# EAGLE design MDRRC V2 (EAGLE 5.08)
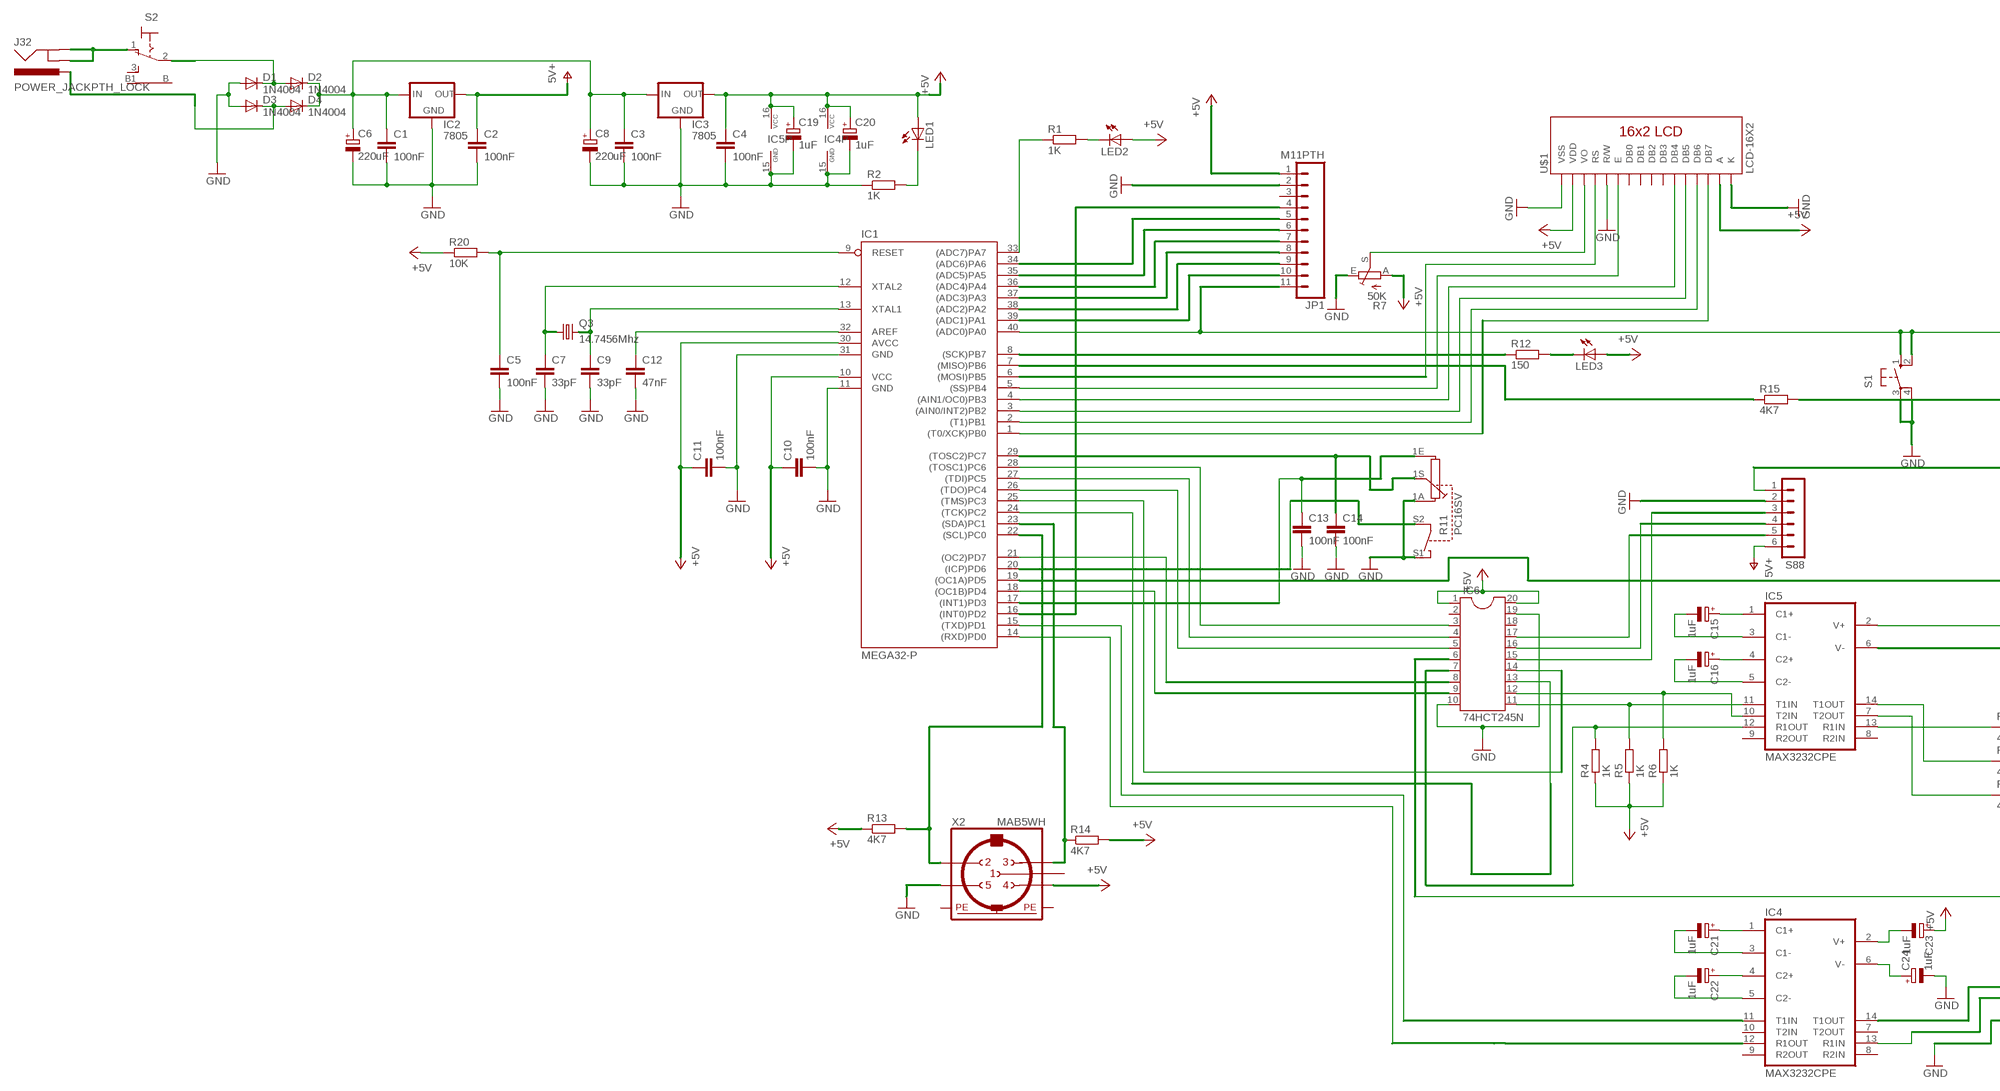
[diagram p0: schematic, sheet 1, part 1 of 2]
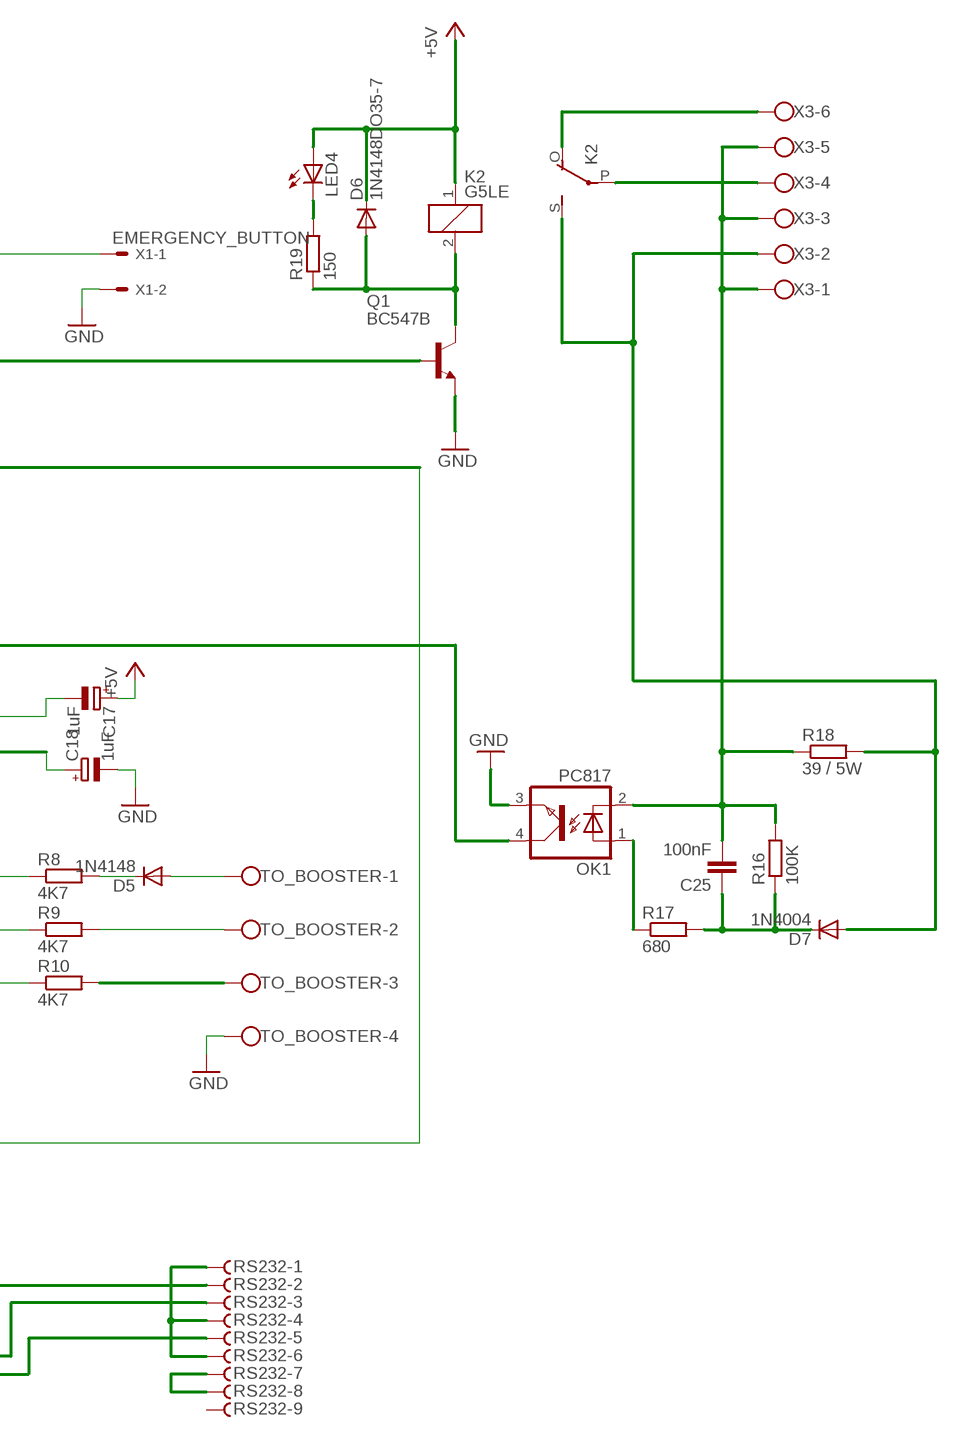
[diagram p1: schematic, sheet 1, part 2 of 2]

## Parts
C1  100nF  C-EU025-025X050  [C025-025X050]
C2  100nF  C-EU025-025X050  [C025-025X050]
C3  100nF  C-EU025-025X050  [C025-025X050]
C4  100nF  C-EU025-025X050  [C025-025X050]
C5  100nF  C-EU025-025X050  [C025-025X050]
C6  220uF  CPOL-EUE2.5-5  [E2,5-5]
C7  33pF  C-EU025-025X050  [C025-025X050]
C8  220uF  CPOL-EUE2.5-5  [E2,5-5]
C9  33pF  C-EU025-025X050  [C025-025X050]
C10  100nF  C-EU025-025X050  [C025-025X050]
C11  100nF  C-EU025-025X050  [C025-025X050]
C12  47nF  C-EU025-025X050  [C025-025X050]
C13  100nF  C-EU025-025X050  [C025-025X050]
C14  100nF  C-EU025-025X050  [C025-025X050]
C15  1uF  CPOL-EUE1.8-4  [E1,8-4]
C16  1uF  CPOL-EUE1.8-4  [E1,8-4]
C17  1uF  CPOL-EUE1.8-4  [E1,8-4]
C18  1uF  CPOL-EUE1.8-4  [E1,8-4]
C19  1uF  CPOL-EUE1.8-4  [E1,8-4]
C20  1uF  CPOL-EUE1.8-4  [E1,8-4]
C21  1uF  CPOL-EUE1.8-4  [E1,8-4]
C22  1uF  CPOL-EUE1.8-4  [E1,8-4]
C23  1uF  CPOL-EUE1.8-4  [E1,8-4]
C24  1uF  CPOL-EUE1.8-4  [E1,8-4]
C25  100nF  C-EU025-025X050  [C025-025X050]
D1  1N4004  [DO41-10]
D2  1N4004  [DO41-10]
D3  1N4004  [DO41-10]
D4  1N4004  [DO41-10]
D5  1N4148  1N4148DO35-10  [DO35-10]
D6  1N4148DO35-7  [DO35-7]
D7  1N4004  [DO41-10]
IC1  MEGA32-P  [DIL40]
IC2  7805  78XXS  [78XXS]
IC3  7805  78XXS  [78XXS]
IC4  MAX3232CPE  [DIL16]
IC5  MAX3232CPE  [DIL16]
IC6  74HCT245N  DIL20  [DIL20]
J32  POWER_JACKPTH_LOCK  [POWER_JACK_PTH_LOCK]
JP1  M11PTH  [1X11]
K2  G5LE  [G5LE]
LED1  LED3MM  [LED3MM]
LED2  LED3MM  [LED3MM]
LED3  LED3MM  [LED3MM]
LED4  LED3MM  [LED3MM]
OK1  PC817  [DIL04]
Q1  BC547B  [TO92]
Q3  14.7456Mhz  CRYSTALHC18U-V  [HC18U-V]
R1  1K  R-EU_0207/10  [0207/10]
R2  1K  R-EU_0207/10  [0207/10]
R4  1K  R-EU_0207/10  [0207/10]
R5  1K  R-EU_0207/10  [0207/10]
R6  1K  R-EU_0207/10  [0207/10]
R7  50K  TRIM_EU-CA6V  [CA6V]
R8  4K7  R-EU_0207/10  [0207/10]
R9  4K7  R-EU_0207/10  [0207/10]
R10  4K7  R-EU_0207/10  [0207/10]
R11  PC16SV  [PC16SV]
R12  150  R-EU_0207/10  [0207/10]
R13  4K7  R-EU_0207/10  [0207/10]
R14  4K7  R-EU_0207/10  [0207/10]
R15  4K7  R-EU_0207/10  [0207/10]
R16  100K  R-EU_0207/10  [0207/10]
R17  680  R-EU_0207/10  [0207/10]
R18  39 / 5W  R-EU_V235/17  [V235/17]
R19  150  R-EU_0207/10  [0207/10]
R20  10K  R-EU_0207/2V  [0207/2V]
RS232  F09HPS  [F09HP]
S1  10-XX  [B3F-10XX]
S2  LPV-1  [LPV-1]
S88  MA06-1  [MA06-1]
TO_BOOSTER  W237-04P  [W237-4P]
U$1  LCD-16X2  [LCD-16X2]
X1  EMERGENCY_BUTTON  22-23-2021  [22-23-2021]
X2  MAB5WH  [MAB5WH]
X3  W237-06P  [W237-6P]

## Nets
+5V: C4.1 C10.1 C11.1 C17.+ C19.+ C20.+ C23.+ D6.C IC1.10(VCC) IC1.30(AVCC) IC3.OUT IC4.16(VCC) IC5.16(VCC) IC6.1 IC6.20 JP1.1 K2.1 LED1.A LED2.A LED3.A LED4.A R4.1 R5.1 R6.1 R7.A R13.1 R14.2 R20.1 U$1.2(VDD) U$1.15(A) X2.4
GND: C1.2 C2.2 C3.2 C4.2 C5.2 C6.- C7.2 C8.- C9.2 C10.2 C11.2 C12.2 C13.2 C14.2 C18.- C19.- C20.- C24.- D1.A D3.A IC1.11(GND) IC1.31(GND) IC2.GND IC3.GND IC4.15(GND) IC5.15(GND) IC6.10 IC6.19 JP1.2 OK1.3(EMIT) Q1.1(E) R2.1 R7.E R11.1A R11.S1 RS232.5 S1.3(P) S1.4(P1) S88.2 TO_BOOSTER.4 U$1.1(VSS) U$1.5(R/W) U$1.16(K) X1.2 X2.5
N$1: D1.C D2.A S2.2(P)
N$2: D3.C D4.A J32.PWR
N$3: C7.1 IC1.12(XTAL2) Q3.1
N$4: C1.1 C3.1 C6.+ C8.+ D2.C D4.C IC2.IN IC3.IN
N$5: C9.1 IC1.13(XTAL1) Q3.2
N$6: C12.1 IC1.32(AREF)
N$7: LED1.K(C) R2.2
N$8: C5.1 IC1.9(RESET) R20.2
N$9: IC1.33((ADC7)PA7) R1.1
N$10: LED2.K(C) R1.2
N$11: IC1.40((ADC0)PA0) JP1.11 S1.1(S) S1.2(S1) X1.1
N$12: IC1.8((SCK)PB7) R12.1
N$13: LED3.K(C) R12.2
N$14: IC5.12(R1OUT) IC6.7 R4.2
N$15: IC1.28((TOSC1)PC6) IC6.3
N$16: IC1.27((TDI)PC5) IC6.4
N$17: IC1.26((TDO)PC4) IC6.5
N$18: IC1.21((OC2)PD7) IC6.8
N$19: IC1.18((OC1B)PD4) IC6.9
N$20: IC1.25((TMS)PC3) IC6.14
N$23: IC5.11(T1IN) IC6.11 R5.2
N$24: IC5.10(T2IN) IC6.12 R6.2
N$27: C16.- IC5.5(C2-)
N$28: C15.- IC5.3(C1-)
N$29: C15.+ IC5.1(C1+)
N$30: C16.+ IC5.4(C2+)
N$31: C17.- IC5.2(V+)
N$34: IC6.15 S88.3
N$37: C21.+ IC4.1(C1+)
N$38: C21.- IC4.3(C1-)
N$39: C22.+ IC4.4(C2+)
N$40: C22.- IC4.5(C2-)
N$41: C23.- IC4.2(V+)
N$42: C24.+ IC4.6(V-)
N$43: IC1.15((TXD)PD1) IC4.11(T1IN)
N$45: IC4.14(T1OUT) RS232.2
N$46: IC4.13(R1IN) RS232.3
N$47: IC1.1((T0/XCK)PB0) U$1.14(DB7)
N$48: IC1.2((T1)PB1) U$1.13(DB6)
N$49: IC1.3((AIN0/INT2)PB2) U$1.12(DB5)
N$50: IC1.4((AIN1/OC0)PB3) U$1.11(DB4)
N$51: IC1.5((SS)PB4) U$1.6(E)
N$52: IC1.6((MOSI)PB5) U$1.4(RS)
N$53: R7.S U$1.3(VO)
N$54: IC5.14(T1OUT) R9.1
N$55: IC5.7(T2OUT) R10.1
N$56: IC5.13(R1IN) R8.1
N$57: R10.2 TO_BOOSTER.3
N$58: R9.2 TO_BOOSTER.2
N$59: D5.C R8.2
N$60: D5.A TO_BOOSTER.1
N$62: IC6.16 S88.4
N$63: IC6.17 S88.5
N$64: IC6.6 S88.1
N$67: IC1.7((MISO)PB6) R15.1
N$68: RS232.1 RS232.4 RS232.6
N$69: RS232.7 RS232.8
N$72: IC1.39((ADC1)PA1) JP1.10
N$73: IC1.38((ADC2)PA2) JP1.9
N$74: IC1.14((RXD)PD0) IC4.12(R1OUT)
N$75: IC1.37((ADC3)PA3) JP1.8
N$77: IC1.24((TCK)PC2) IC6.13
N$82: IC1.22((SCL)PC0) R13.2 X2.2
N$83: J32.GND J32.GNDBREAK S2.1(O)
N$84: IC1.20((ICP)PD6) R11.S2
N$85: C13.1 IC1.17((INT1)PD3) R11.1E
N$86: C14.1 IC1.29((TOSC2)PC7) R11.1S
N$87: IC1.36((ADC4)PA4) JP1.7
N$88: IC1.19((OC1A)PD5) OK1.4(COL)
N$91: IC1.35((ADC5)PA5) JP1.6
N$92: IC1.34((ADC6)PA6) JP1.5
N$96: IC1.16((INT0)PD2) JP1.4
N$98: IC1.23((SDA)PC1) R14.1 X2.3
N$100: C18.+ IC5.6(V-)
N$101: Q1.2(B) R15.2
N$102: D6.A K2.2 Q1.3(C) R19.1
N$105: K2.P(2:P) X3.4
N$108: K2.O(2:O) X3.6
N$113: C25.2 OK1.2(C) R16.2 R18.1 X3.1 X3.3 X3.5
N$114: OK1.1(A) R17.1
N$115: C25.1 D7.C R16.1 R17.2
N$116: D7.A K2.S(2:S) R18.2 X3.2
N$117: LED4.K(C) R19.2
V+: C2.1 IC2.OUT S88.6 ; supply symbol labelled 5V+
Unconnected: IC4.7(T2OUT) IC4.8(R2IN) IC4.9(R2OUT) IC4.10(T2IN) IC5.8(R2IN) IC5.9(R2OUT) IC6.2 IC6.18 JP1.3 RS232.9 S2.3(S) S2.B S2.B1 U$1.7(DB0) U$1.8(DB1) U$1.9(DB2) U$1.10(DB3) X2.1

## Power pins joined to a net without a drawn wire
PE: X2.PE X2.PE@(PE)

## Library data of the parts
C1-C5 C7 C9-C14 C25 = rcl:C-EU: CAPACITOR, European symbol
C6 C8 C15-C24 = rcl:CPOL-EU: POLARIZED CAPACITOR, European symbol
D1-D4 D7 = diode:1N4004: DIODE
D5 D6 = diode:1N4148: DIODE
IC1 = atmel:MEGA32-P: MICROCONTROLLER 32 Kbytes FLASH 2 Kbytes SRAM 1 Kbytes EEPROM USART 8-channel 10 bit ADC Source: www.atmel.com .. doc2503.pdf
IC2 IC3 = v-reg:78XXS: VOLTAGE REGULATOR
IC4 IC5 = maxim:MAX3232*: True RS-232 Transceivers 3.0V to 5.5V, Low-Power up to 1Mbps, Using Four 0.1µF External Capacitors Source: http://pdfserv.maxim-ic.com/en/ds/MAX3222-MAX3241.pdf
IC6 = ic-package:DIL20: Dual In Line / Socket
J32 = SparkFun:POWER_JACK: Power Jack This is the standard 5.5mm barrel jack for power. The PTH is the most common, proven, reliable, footprint. All others are experimental. The Slot footprint only works if the mill layer is transmitted to the PCB fab house so be warned. Spark Fun Electronics SKU : PRT-00119. Mating wall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
JP1 = SparkFun:M11: Header 11 Standard 11-pin 0.1" header. Use with straight break away headers (SKU : PRT-00116), right angle break away headers (PRT-00553), swiss pins (PRT-00743), machine pins (PRT-00117), and female headers (PRT-00115).
K2 = relay:G5LE: RELAY 1 x switch, 10 A/120 V AC, 8 A/30 V DC, Omron
LED1-LED4 = led:LED: LED
OK1 = optocoupler:PC817: SHARP OPTO COUPLER
Q1 = transistor-npn:BC547*: NPN Transistor
Q3 = crystal:CRYSTAL: CRYSTAL
R1 R2 R4-R6 R8-R10 R12-R14 R16 R17 R19 R20 = rcl:R-EU_: RESISTOR, European symbol
R7 = pot:TRIM_EU-: POTENTIOMETER
R11 = rotary_voti:PC16SV: POTENTIOMETER vertical single carbon potentiometer with switch, 16 mm
R15 R18 = resistor:R-EU_: RESISTOR, European symbol
RS232 = con-subd:F09?S: SUB-D
S1 = switch-omron:10-XX: OMRON SWITCH
S2 = switch:LPV-1: TOGGLE SWITCH
S88 = con-lstb:MA06-1: PIN HEADER
TO_BOOSTER = con-wago-508:W237-04P: WAGO SREW CLAMP
U$1 = SparkFun:LCD-16X2
X1 = con-molex:22-23-2021: .100" (2.54mm) Center Header - 2 Pin
X2 = con_midi:MAB5WH: Female CONNECTOR 5 pins with shield, horizontal (DIN 45327)
X3 = con-wago-508:W237-06P: WAGO SREW CLAMP

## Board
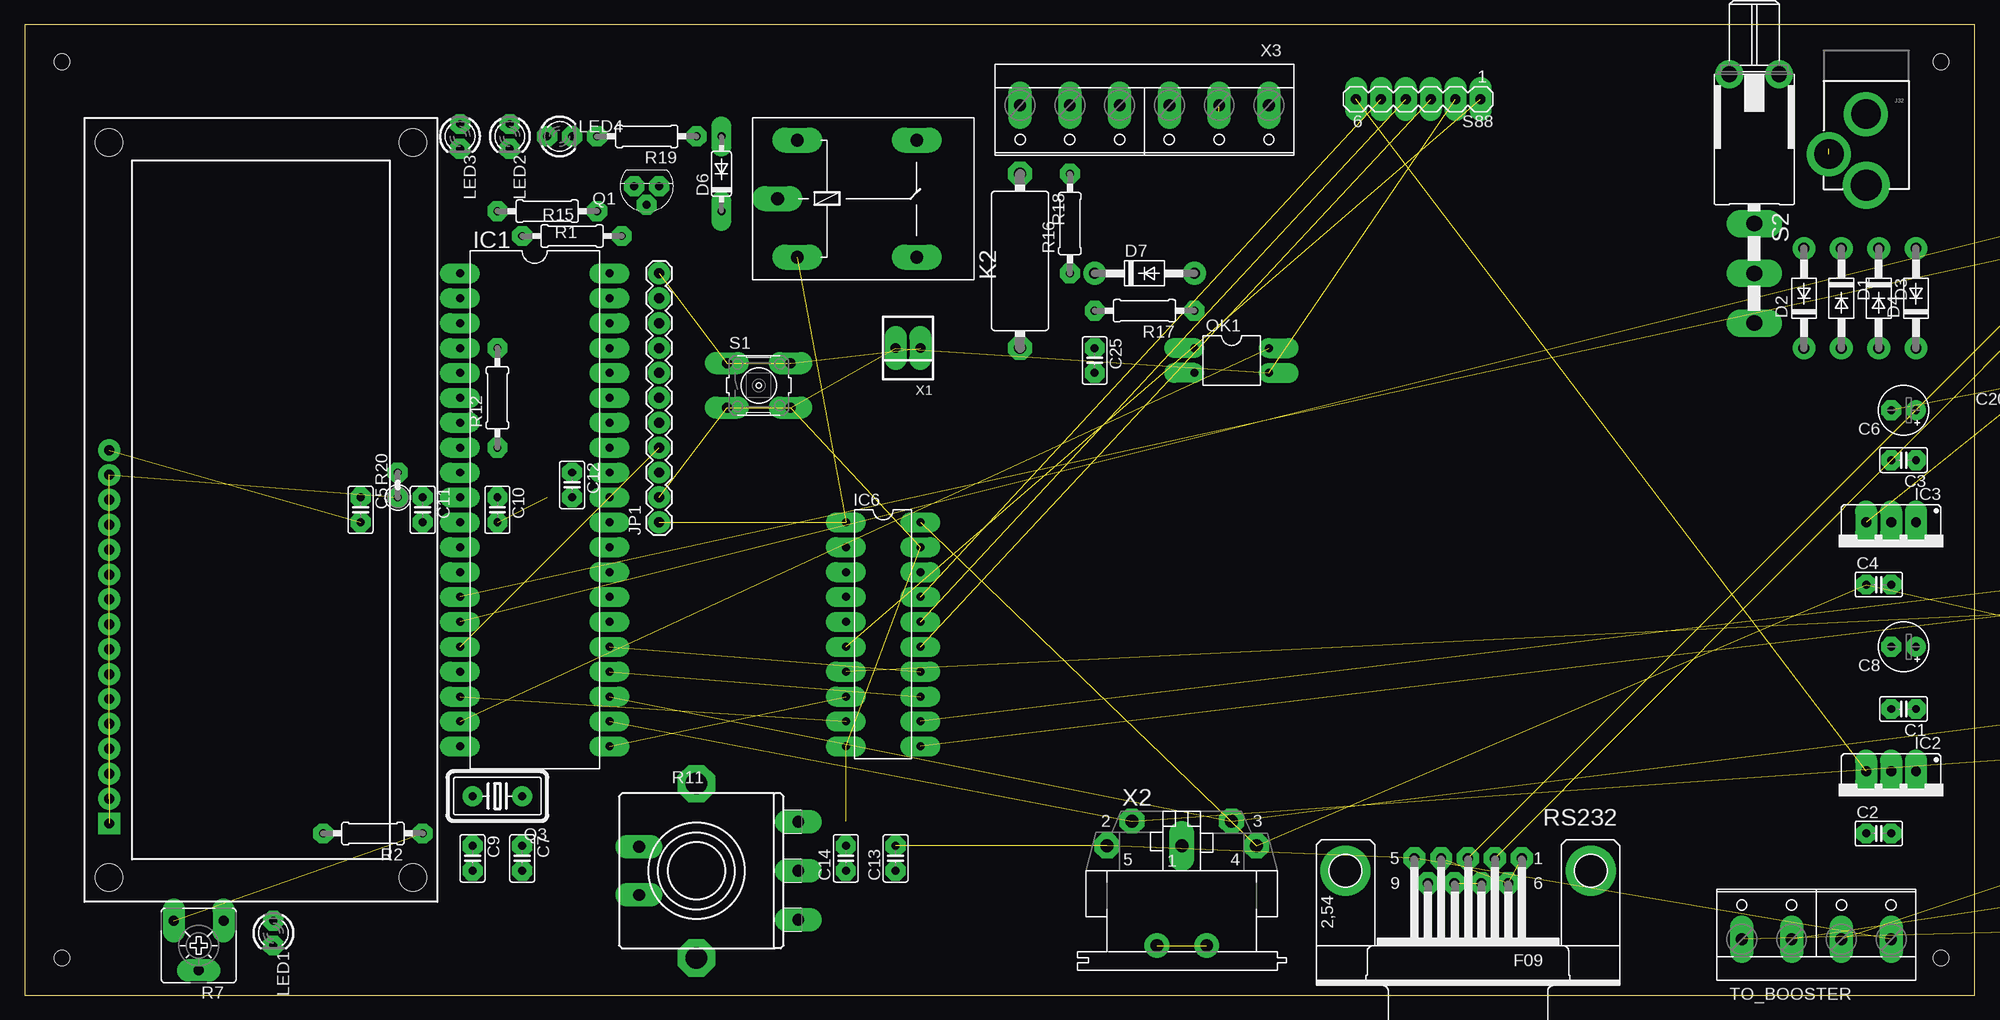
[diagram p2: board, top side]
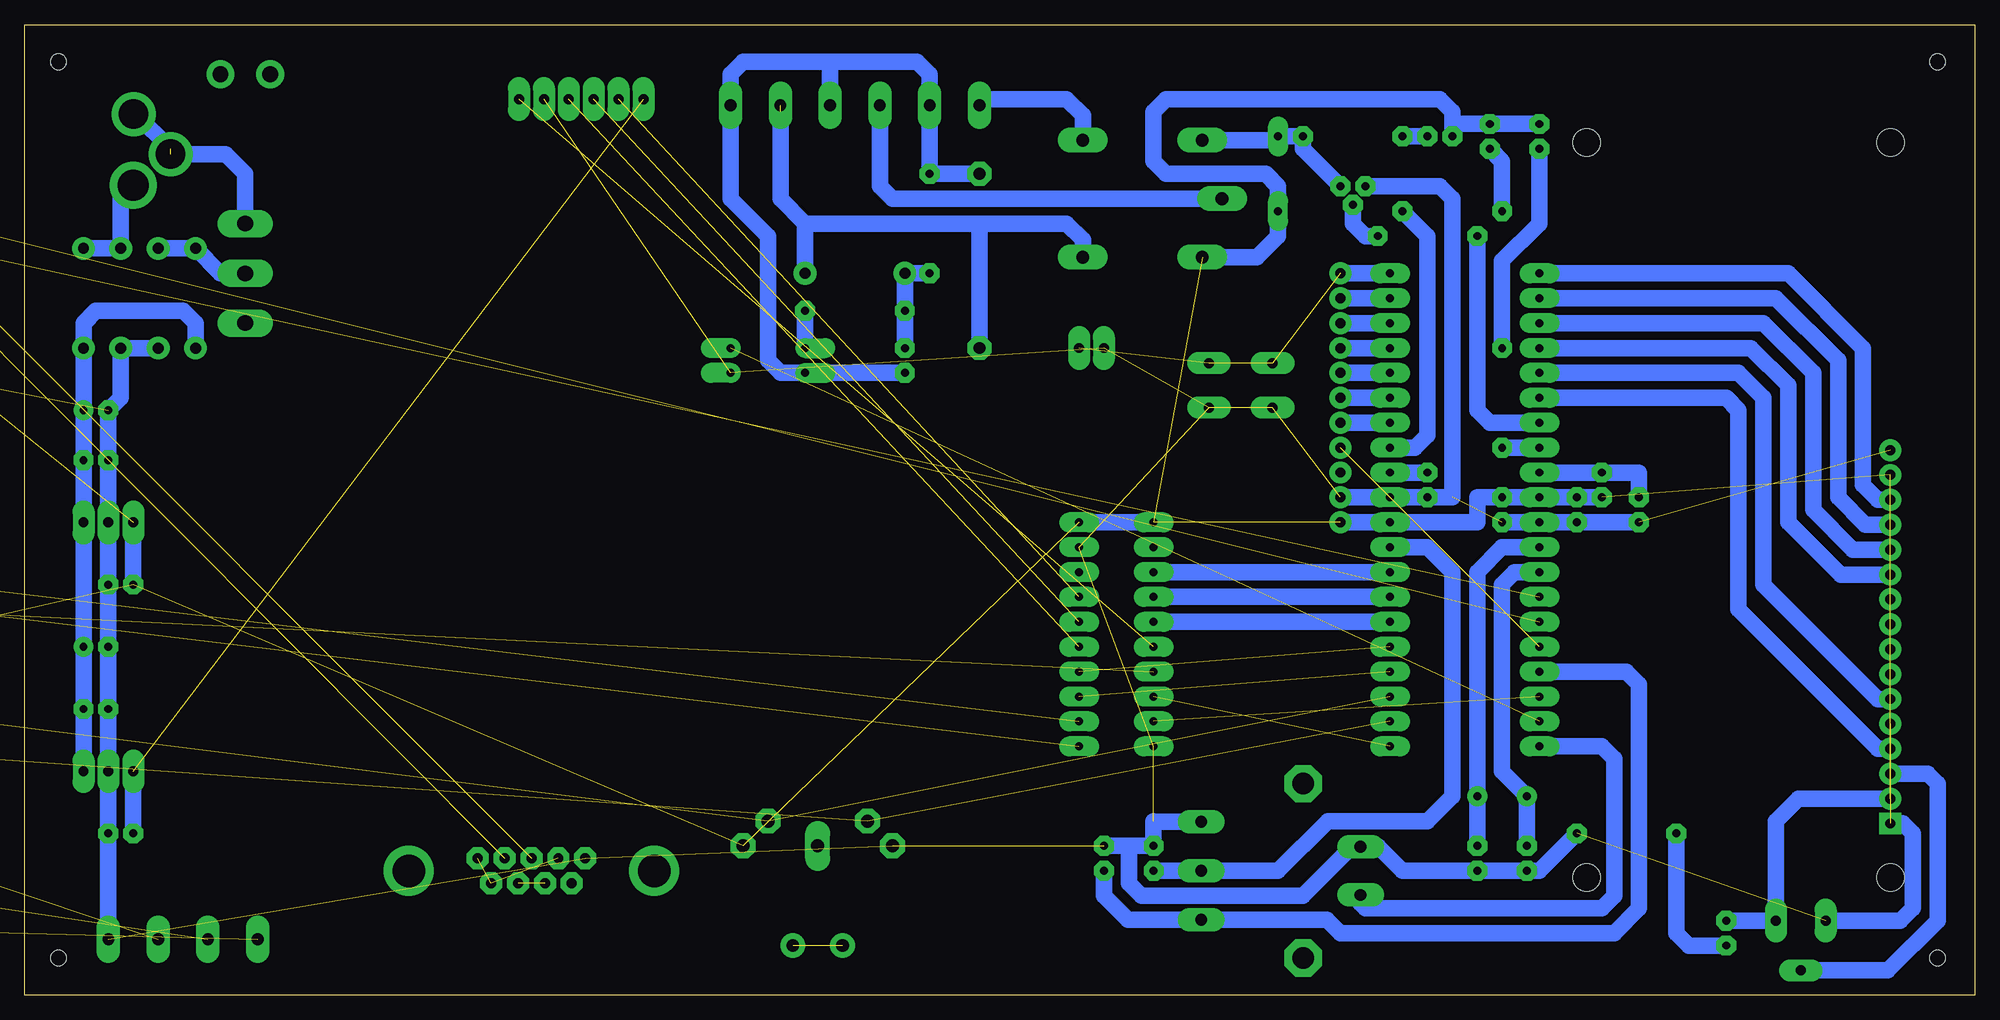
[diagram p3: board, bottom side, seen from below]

Size 199.06 x 99.05 mm. Coordinates in mm from the lower left corner, seen from the top.
Outline: 0,0 199.06,0 199.06,99.05 0,99.05 0,0
Copper layers (1*16): Top 1mm / dielectric 1.5mm / Bottom 1mm
Design rules "DRC settings for  milling": minimum track width 1.5mm, minimum drill 26mil, track to track 0.5mm, track to pad 0.5mm, pad to pad 0.5mm, via to via 0.5mm, smd to smd 8mil, copper to edge 0.6mm, drill to drill 0.6mm, minimum pad ring 0.61mm, minimum via ring 1.2mm, stop-mask expansion 4mil, vias tented up to drill 0mil, thermal gap 10mil
Holes 1.6 mm at 3.81,95.25 3.81,3.81 195.58,3.81 195.58,95.25

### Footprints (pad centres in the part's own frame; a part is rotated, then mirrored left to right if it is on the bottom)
C025-025X050 = drill 0.813 octagon: 1 -1.27,0; 2 1.27,0
E2,5-5 = drill 0.813 pad 1.6 round: + -1.27,0 | drill 0.813 pad 1.6 octagon: - 1.27,0
E1,8-4 = drill 0.711 pad 1.168 round: + -0.889,0 | drill 0.711 pad 1.168 octagon: - 0.889,0
DO41-10 = drill 1.118 round: A 5.08,0; C -5.08,0
DO35-10 = drill 0.813 long: A 5.08,0; C -5.08,0
DO35-7 = drill 0.813 long: A 3.81,0; C -3.81,0
DIL40 = drill 0.813 long: 1 -24.13,-7.62; 2 -21.59,-7.62; 3 -19.05,-7.62; 4 -16.51,-7.62; 5 -13.97,-7.62; 6 -11.43,-7.62; 7 -8.89,-7.62; 8 -6.35,-7.62; 9 -3.81,-7.62; 10 -1.27,-7.62; 11 1.27,-7.62; 12 3.81,-7.62; 13 6.35,-7.62; 14 8.89,-7.62; 15 11.43,-7.62; 16 13.97,-7.62; 17 16.51,-7.62; 18 19.05,-7.62; 19 21.59,-7.62; 20 24.13,-7.62; 21 24.13,7.62; 22 21.59,7.62; 23 19.05,7.62; 24 16.51,7.62; 25 13.97,7.62; 26 11.43,7.62; 27 8.89,7.62; 28 6.35,7.62; 29 3.81,7.62; 30 1.27,7.62; 31 -1.27,7.62; 32 -3.81,7.62; 33 -6.35,7.62; 34 -8.89,7.62; 35 -11.43,7.62; 36 -13.97,7.62; 37 -16.51,7.62; 38 -19.05,7.62; 39 -21.59,7.62; 40 -24.13,7.62
78XXS = drill 1.016 long: GND 0,-2.54; IN -2.54,-2.54; OUT 2.54,-2.54
DIL16 = drill 0.813 long: 1 -8.89,-3.81; 2 -6.35,-3.81; 3 -3.81,-3.81; 4 -1.27,-3.81; 5 1.27,-3.81; 6 3.81,-3.81; 7 6.35,-3.81; 8 8.89,-3.81; 9 8.89,3.81; 10 6.35,3.81; 11 3.81,3.81; 12 1.27,3.81; 13 -1.27,3.81; 14 -3.81,3.81; 15 -6.35,3.81; 16 -8.89,3.81
DIL20 = drill 0.813 long: 1 -11.43,-3.81; 2 -8.89,-3.81; 3 -6.35,-3.81; 4 -3.81,-3.81; 5 -1.27,-3.81; 6 1.27,-3.81; 7 3.81,-3.81; 8 6.35,-3.81; 9 8.89,-3.81; 10 11.43,-3.81; 11 11.43,3.81; 12 8.89,3.81; 13 6.35,3.81; 14 3.81,3.81; 15 1.27,3.81; 16 -1.27,3.81; 17 -3.81,3.81; 18 -6.35,3.81; 19 -8.89,3.81; 20 -11.43,3.81
POWER_JACK_PTH_LOCK = drill 2.997 round: GND 0.025,6.608; GNDBREAK 3.812,10.7 | drill 3.2 round: PWR 0,13.878
1X11 = drill 1.016 pad 1.88 round: 1 0,0; 2 2.54,0; 3 5.08,0; 4 7.62,0; 5 10.16,0; 6 12.7,0; 7 15.24,0; 8 17.78,0; 9 20.32,0; 10 22.86,0; 11 25.4,0
G5LE = drill 1.321 long: 1 -7.493,-5.969; 2 -7.493,5.969; O 4.699,5.969; P -9.525,0; S 4.699,-5.969
LED3MM = drill 0.813 octagon: A -1.27,0; K 1.27,0
DIL04 = drill 0.813 offset: 1 -1.27,-3.81; 2 1.27,-3.81; 3 1.27,3.81; 4 -1.27,3.81
TO92 = drill 0.813 octagon: 1 1.27,0; 2 0,1.905; 3 -1.27,0
HC18U-V = drill 0.813 round: 1 -2.54,0; 2 2.54,0
0207/10 = drill 0.813 octagon: 1 -5.08,0; 2 5.08,0
CA6V = drill 1.016 long: A -2.54,-2.54; E 2.54,-2.54; S 0,2.54
PC16SV = drill 1.2 long: 1A -5,10.4; 1E 5,10.4; 1S 0,10.4; S1 -2.46,-5.87; S2 2.46,-5.87 | drill 2.2 pad 3.81 octagon: P$1 -8.89,0; P$2 8.89,0
V235/17 = drill 1.194 octagon: 1 -8.89,0; 2 8.89,0
0207/2V = drill 0.813 octagon: 1 -1.27,0; 2 1.27,0
F09HP = drill 1.016 octagon: 1 -5.486,-1.27; 2 -2.743,-1.27; 3 0,-1.27; 4 2.743,-1.27; 5 5.486,-1.27; 6 -4.115,1.27; 7 -1.372,1.27; 8 1.372,1.27; 9 4.115,1.27 | drill 3.302 pad 5.08 round: G1 -12.522,0; G2 12.522,0
B3F-10XX = drill 1.016 long: 1 -3.251,2.261; 2 3.251,2.261; 3 -3.251,-2.261; 4 3.251,-2.261
LPV-1 = drill 1.6 long: 1 0,15.24; 2 0,20.32; 3 0,25.4 | drill 1.6 pad 2.54 round: B -2.54,0; B1 2.54,0
MA06-1 = drill 1.016 long: 1 -6.35,0; 2 -3.81,0; 3 -1.27,0; 4 1.27,0; 5 3.81,0; 6 6.35,0
W237-4P = drill 1.194 long: 1 -7.62,-0.635; 2 -2.54,-0.635; 3 2.54,-0.635; 4 7.62,-0.635
LCD-16X2 = drill 1.016 square: 1 -32,15.5 | drill 1.016 round: 2 -29.46,15.5; 3 -26.92,15.5; 4 -24.38,15.5; 5 -21.84,15.5; 6 -19.3,15.5; 7 -16.76,15.5; 8 -14.22,15.5; 9 -11.68,15.5; 10 -9.14,15.5; 11 -6.6,15.5; 12 -4.06,15.5; 13 -1.52,15.5; 14 1.02,15.5; 15 3.56,15.5; 16 6.1,15.5 | hole 2.8: -37.5,15.5; -37.5,-15.5; 37.5,15.5; 37.5,-15.5
22-23-2021 = drill 1 long: 1 -1.27,0; 2 1.27,0
MAB5WH = drill 1.321 long: 1 0,5.08 | drill 1.321 octagon: 2 -5.08,7.62; 3 5.08,7.62; 4 7.62,5.08; 5 -7.62,5.08 | drill 1.321 round: PE -2.54,-5.08; PE@ 2.54,-5.08
W237-6P = drill 1.194 long: 1 -12.7,-0.635; 2 -7.62,-0.635; 3 -2.54,-0.635; 4 2.54,-0.635; 5 7.62,-0.635; 6 12.7,-0.635

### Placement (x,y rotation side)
C1  191.77,29.21 180 top
C2  189.23,16.51 0 top
C3  191.77,54.61 180 top
C4  189.23,41.91 0 top
C5  34.29,49.53 270 top
C6  191.77,59.69 180 top
C7  50.8,13.97 270 top
C8  191.77,35.56 180 top
C9  45.72,13.97 270 top
C10  48.26,49.53 270 top
C11  40.64,49.53 270 top
C12  55.88,52.07 270 top
C13  88.9,13.97 90 top
C14  83.82,13.97 90 top
C15  not placed on the board
C16  not placed on the board
C17  not placed on the board
C18  not placed on the board
C19  not placed on the board
C20  not placed on the board
C21  not placed on the board
C22  not placed on the board
C23  not placed on the board
C24  not placed on the board
C25  109.22,64.77 270 top
D1  185.42,71.12 270 top
D2  181.61,71.12 90 top
D3  189.23,71.12 270 top
D4  193.04,71.12 90 top
D5  not placed on the board
D6  71.12,83.82 90 top
D7  114.3,73.66 0 top
IC1  52.07,49.53 270 top
IC2  190.5,20.32 180 top
IC3  190.5,45.72 180 top
IC4  not placed on the board
IC5  not placed on the board
IC6  87.63,36.83 270 top
J32  187.96,96.52 180 top
JP1  64.77,48.26 90 top
K2  86.36,81.28 0 top
LED1  25.4,6.35 270 top
LED2  49.53,87.63 270 top
LED3  44.45,87.63 270 top
LED4  54.61,87.63 0 top
OK1  123.19,64.77 270 top
Q1  63.5,82.55 180 top
Q3  48.26,20.32 180 top
R1  53.34,80.01 180 top
R2  35.56,16.51 180 top
R4  not placed on the board
R5  not placed on the board
R6  not placed on the board
R7  17.78,5.08 180 top
R8  not placed on the board
R9  not placed on the board
R10  not placed on the board
R11  68.58,12.7 270 top
R12  48.26,60.96 90 top
R13  not placed on the board
R14  not placed on the board
R15  55.88,77.47 0 top
R16  106.68,78.74 90 top
R17  114.3,69.85 180 top
R18  101.6,74.93 270 top
R19  63.5,87.63 180 top
R20  38.1,52.07 90 top
RS232  147.32,12.7 180 top
S1  74.93,62.23 0 top
S2  176.53,93.98 180 top
S88  142.24,91.44 180 top
TO_BOOSTER  182.88,6.35 0 top
U$1  24.13,49.53 90 top
X1  90.17,66.04 180 top
X2  118.11,10.16 0 top
X3  114.3,90.17 180 top

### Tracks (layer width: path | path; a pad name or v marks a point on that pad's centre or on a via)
+5V  (17 unrouted)
  Bottom 1.676: JP1.1 IC1.30 50.8,48.26 50.8,50.8 C10.1 IC1.10 C11.1 R20.1 | K2.1 73.28,75.31 71.12,77.47 D6.C 71.12,82.55 72.39,83.82 82.55,83.82 83.82,85.09 83.82,90.17 82.55,91.44 54.61,91.44 53.34,90.17 53.34,88.9 | 53.34,88.9 LED4.A | C4.1 IC3.OUT | LED1.A R7.A 20.32,17.78 18.03,20.07 U$1.2 | LED3.A LED2.A 53.34,88.9 | IC6.1 IC6.20
GND  (21 unrouted)
  Bottom 1.676: JP1.2 IC1.31 C12.2 53.34,50.8 53.34,54.61 53.34,57.15 53.34,81.28 54.61,82.55 Q1.1 | C5.2 C11.2 IC1.11 C10.2 | D1.A D3.A 189.23,60.96 C6.- C3.2 IC3.GND C4.2 C8.- C1.2 IC2.GND C2.2 190.5,6.35 TO_BOOSTER.4 | 86.36,15.24 C14.2 83.82,17.78 83.74,17.7 R11.1A | 86.36,15.24 C13.2 | R2.1 44.45,12.7 C9.2 C7.2 58.42,12.7 60.88,15.16 R11.S1 63.58,15.16 68.58,10.16 85.09,10.16 86.36,11.43 86.36,15.24 | R7.E 7.62,7.62 6.35,8.89 6.35,16.51 7.37,17.53 U$1.1
N$1
  Bottom 1.676: S2.2 179.07,73.66 D2.A D1.C
N$2
  Bottom 1.676: J32.PWR 187.96,82.55 189.23,81.28 D3.C D4.A
N$3
  Bottom 1.676: IC1.12 48.26,45.72 50.8,43.18 50.8,22.86 Q3.1 C7.1
N$4
  Bottom 1.676: D2.C 181.61,68.58 182.88,69.85 191.77,69.85 193.04,68.58 D4.C C6.+ C3.1 IC3.IN C8.+ C1.1 IC2.IN
N$5
  Bottom 1.676: C9.1 Q3.2 48.26,22.86 48.26,41.91 46.99,43.18 IC1.13
N$6
  Bottom 1.676: C12.1 IC1.32
N$7
  Bottom 1.676: LED1.K 29.21,5.08 30.48,6.35 R2.2
N$8
  Bottom 1.676: IC1.9 R20.2 34.29,53.34 C5.1
N$9
  Bottom 1.676: IC1.33 57.15,55.88 55.88,57.15 55.88,77.47 R1.1
N$10
  Bottom 1.676: R1.2 48.26,85.09 LED2.K
N$11  (3 unrouted)
  Bottom 1.676: IC1.40 JP1.11
N$12
  Bottom 1.676: IC1.8 R12.1
N$13
  Bottom 1.676: R12.2 48.26,74.93 44.45,78.74 LED3.K
N$14  (2 unrouted)
N$15
  Bottom 1.676: IC1.28 IC6.3
N$16
  Bottom 1.676: IC1.27 IC6.4
N$17
  Bottom 1.676: IC1.26 IC6.5
N$18  (1 unrouted)
N$19  (1 unrouted)
N$20  (1 unrouted)
N$23  (2 unrouted)
N$24  (2 unrouted)
N$27  (1 unrouted)
N$28  (1 unrouted)
N$29  (1 unrouted)
N$30  (1 unrouted)
N$31  (1 unrouted)
N$34  (1 unrouted)
N$37  (1 unrouted)
N$38  (1 unrouted)
N$39  (1 unrouted)
N$40  (1 unrouted)
N$41  (1 unrouted)
N$42  (1 unrouted)
N$43  (1 unrouted)
N$45  (1 unrouted)
N$46  (1 unrouted)
N$47
  Bottom 1.676: U$1.14 9.91,50.55 11.43,52.07 11.43,66.04 19.05,73.66 IC1.1
N$48
  Bottom 1.676: U$1.13 11.18,48.01 13.97,50.8 13.97,64.77 20.32,71.12 IC1.2
N$49
  Bottom 1.676: U$1.12 12.45,45.47 16.51,49.53 16.51,63.5 21.59,68.58 IC1.3
N$50
  Bottom 1.676: U$1.11 13.72,42.93 19.05,48.26 19.05,62.23 22.86,66.04 IC1.4
N$51
  Bottom 1.676: IC1.5 24.13,63.5 21.59,60.96 21.59,41.91 9.91,30.23 U$1.6
N$52
  Bottom 1.676: U$1.4 9.91,25.15 24.13,39.37 24.13,59.69 25.4,60.96 IC1.6
N$53
  Bottom 1.676: R7.S 8.89,2.54 3.81,7.62 3.81,21.59 4.83,22.61 U$1.3
N$54  (1 unrouted)
N$55  (1 unrouted)
N$56  (1 unrouted)
N$57  (1 unrouted)
N$58  (1 unrouted)
N$59  (1 unrouted)
N$60  (1 unrouted)
N$62  (1 unrouted)
N$63  (1 unrouted)
N$64  (1 unrouted)
N$67
  Bottom 1.676: IC1.7 49.53,58.42 50.8,59.69 R15.1
N$68  (2 unrouted)
N$69  (1 unrouted)
N$72
  Bottom 1.676: IC1.39 JP1.10
N$73
  Bottom 1.676: IC1.38 JP1.9
N$74  (1 unrouted)
N$75
  Bottom 1.676: IC1.37 JP1.8
N$77  (1 unrouted)
N$82  (2 unrouted)
N$83  (1 unrouted)
  Bottom 1.676: J32.GND 187.7,89.91 184.15,86.36 | J32.GNDBREAK 178.53,85.82 176.53,83.82 S2.1
N$84
  Bottom 1.676: R11.S2 62.71,9.37 62.23,8.89 38.1,8.89 36.83,10.16 36.83,24.13 38.1,25.4 IC1.20
N$85
  Bottom 1.676: C13.1 88.9,10.16 86.44,7.7 R11.1E 66.12,7.7 64.77,6.35 36.83,6.35 34.29,8.89 34.29,31.75 35.56,33.02 IC1.17
N$86
  Bottom 1.676: C14.1 R11.1S 71.12,12.7 66.04,17.78 55.88,17.78 53.34,20.32 53.34,43.18 55.88,45.72 IC1.29
N$87
  Bottom 1.676: IC1.36 JP1.7
N$88  (1 unrouted)
N$91
  Bottom 1.676: IC1.35 JP1.6
N$92
  Bottom 1.676: IC1.34 JP1.5
N$96  (1 unrouted)
N$98  (2 unrouted)
N$100  (1 unrouted)
N$101
  Bottom 1.676: R15.2 62.23,77.47 63.5,78.74 Q1.2
N$102
  Bottom 1.676: K2.2 71.5,87.25 D6.A R19.1 68.58,86.36 Q1.3
N$105
  Bottom 1.676: K2.P 110.49,81.28 111.76,82.55 X3.4
N$108
  Bottom 1.676: K2.O 91.06,89.79 92.71,91.44 100.97,91.44 X3.6
N$113
  Bottom 1.676: 116.84,95.25 107.95,95.25 106.68,93.98 X3.5 R16.2 R18.1 | 116.84,95.25 125.73,95.25 127,93.98 X3.1 127,81.28 123.19,77.47 123.19,64.77 121.92,63.5 OK1.2 C25.2 | 116.84,95.25 X3.3
N$114
  Bottom 1.676: OK1.1 R17.1
N$115
  Bottom 1.676: R16.1 D7.C R17.2 C25.1
N$116  (1 unrouted)
  Bottom 1.676: 121.92,90.17 121.92,81.28 119.38,78.74 | K2.S 91.06,77.09 92.71,78.74 101.6,78.74 | 101.6,78.74 119.38,78.74 | 101.6,78.74 R18.2 | 119.38,78.74 D7.A
N$117
  Bottom 1.676: LED4.K R19.2
PE  (1 unrouted)
V+  (1 unrouted)
  Bottom 1.676: C2.1 IC2.OUT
